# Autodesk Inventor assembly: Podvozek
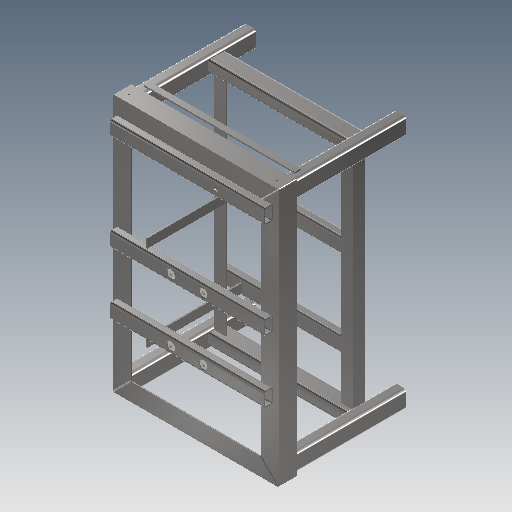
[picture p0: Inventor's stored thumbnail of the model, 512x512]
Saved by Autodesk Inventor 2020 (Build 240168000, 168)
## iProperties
Created: 2025-03
Part Number: Podvozek
Document SubType Name: Assembly
Designer: doma
Mass: 48215.9 g
Surface Area: 25160.2 cm^2
Volume: 6142.15 cm^3
Density: 7.85 g/cm^3
Author: doma
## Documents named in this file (13)
- C:\Users\doma\Desktop\Pásovka záloha\Workgroups\NotInProject\Svařenec podvozek.iam
- C:\Users\doma\Desktop\Pásovka záloha\Workgroups\NotInProject\Podvozek vinkl 870.ipt
- C:\Users\doma\Desktop\Pásovka záloha\Workgroups\NotInProject\Podvozek vinkl 560.ipt
- C:\Users\doma\Desktop\Pásovka záloha\Workgroups\NotInProject\Podvozek jekl 430.ipt
- C:\Users\doma\Desktop\Pásovka záloha\Workgroups\NotInProject\Podvozek jekl 468.ipt
- C:\Users\doma\Desktop\Pásovka záloha\Workgroups\NotInProject\Podvozek vinkl 738.ipt
- C:\Users\doma\Desktop\Pásovka záloha\Workgroups\NotInProject\Podvozek pásovina 508.ipt
- C:\Users\doma\Desktop\Pásovka záloha\Workgroups\NotInProject\Podvozek jekl 458.ipt
- C:\Users\doma\Desktop\Pásovka záloha\Workgroups\NotInProject\Matice kotevní desky.ipt
- C:\Users\doma\Desktop\Pásovka záloha\Workgroups\NotInProject\Podvozek pásovina 320.ipt
- C:\Users\doma\Desktop\Pásovka záloha\Workgroups\NotInProject\Podvozek jekl 520 1.ipt
- C:\Users\doma\Desktop\Pásovka záloha\Workgroups\NotInProject\Podvozek jekl 520 2.ipt
- C:\Users\doma\Documents\Inventor\Content Center Files\R2020\cs-CZ\CSN 02 1741\CSN 02 1741 - 5.ipt
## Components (26 placed, 12 different names)
1. Podvozek vinkl 870:1 — Stejný směr:3, Proti sobě:5, Proti sobě:6, Proti sobě:12, Proti sobě:13, Proti sobě:17, Stejný směr:52, Stejný směr:55, Proti sobě:52
2. Podvozek vinkl 870:2 — Proti sobě:1, Stejný směr:1, Stejný směr:2, Proti sobě:3, Proti sobě:9, Proti sobě:11, Proti sobě:14, Proti sobě:18, Stejný směr:54, Proti sobě:51
3. Podvozek vinkl 560:1 — Proti sobě:1, Stejný směr:1, Stejný směr:3, Proti sobě:6, Proti sobě:7, Proti sobě:8, Proti sobě:16, Proti sobě:20, Proti sobě:51, Proti sobě:52
4. Podvozek vinkl 560:2 — Stejný směr:2, Proti sobě:3, Proti sobě:5, Proti sobě:10, Proti sobě:15, Proti sobě:31, Proti sobě:35
5. Podvozek jekl 430:1 — Proti sobě:9, Proti sobě:11, Stejný směr:5, Proti sobě:16, Proti sobě:23, Stejný směr:14, Proti sobě:28
6. Podvozek jekl 430:2 — Proti sobě:10, Proti sobě:14, Stejný směr:4, Proti sobě:29, Proti sobě:30
7. Podvozek jekl 430:3 — Proti sobě:8, Proti sobě:13, Proti sobě:15, Stejný směr:4, Proti sobě:21, Proti sobě:24
8. Podvozek jekl 430:4 — Proti sobě:7, Proti sobě:12, Stejný směr:5, Proti sobě:22, Proti sobě:27
9. Podvozek jekl 520 1:1 — Stejný směr:6, Proti sobě:17, Proti sobě:19, Proti sobě:20, Proti sobě:44, Proti sobě:45, Proti sobě:48, Stejný směr:53, Stejný směr:54
10. Podvozek jekl 520 1:2 — Stejný směr:6, Proti sobě:19, Stejný směr:38, Proti sobě:42, Proti sobě:43, Proti sobě:49, Stejný směr:53
11. Podvozek jekl 520 2:1 — Proti sobě:18, Proti sobě:35, Stejný směr:55
12. Podvozek jekl 468:1 — Proti sobě:21, Proti sobě:24, Stejný směr:13
13. Podvozek jekl 468:2 — Proti sobě:22, Proti sobě:23, Stejný směr:13, Stejný směr:14, Proti sobě:25, Proti sobě:26, Stejný směr:17
14. Podvozek vinkl 738:1 — Proti sobě:26, Stejný směr:16, Proti sobě:27, Stejný směr:17
15. Podvozek vinkl 738:2 — Proti sobě:25, Stejný směr:16, Proti sobě:28, Proti sobě:32, Proti sobě:33, Proti sobě:34, Proti sobě:50
16. Podvozek pásovina 508:1 — Proti sobě:29, Proti sobě:30, Proti sobě:31
17. Podvozek jekl 458:1 — Stejný směr:18, Proti sobě:32, Proti sobě:33, Stejný směr:50
18. Podvozek jekl 458:2 — Stejný směr:18, Proti sobě:34, Proti sobě:47, Stejný směr:51
19. Matice kotevní desky:1 — Stejný směr:35, Proti sobě:45
20. Matice kotevní desky:2 — Stejný směr:36, Proti sobě:44
21. Matice kotevní desky:3 — Stejný směr:35, Stejný směr:36, Stejný směr:37, Proti sobě:43
22. Matice kotevní desky:4 — Stejný směr:37, Stejný směr:38, Proti sobě:42
23. Podvozek pásovina 320:1 — Stejný směr:48, Stejný směr:49, Proti sobě:47, Proti sobě:48, Stejný směr:51
24. Podvozek pásovina 320:2 — Stejný směr:48, Stejný směr:49, Proti sobě:49, Stejný směr:50, Stejný směr:52
25. CSN 02 1741 5:1 — Stejný směr:56
26. CSN 02 1741 5:2 — Stejný směr:56, Proti sobě:50
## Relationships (67: Mate 43, Flush 24)
- Proti sobě:1 [Mate]: Podvozek vinkl 870:2 ↔ Podvozek vinkl 560:1
- Stejný směr:1 [Flush]: Podvozek vinkl 870:2 ↔ Podvozek vinkl 560:1
- Stejný směr:2 [Flush]: Podvozek vinkl 870:2 ↔ Podvozek vinkl 560:2
- Proti sobě:3 [Mate]: Podvozek vinkl 870:2 ↔ Podvozek vinkl 560:2
- Stejný směr:3 [Flush]: Podvozek vinkl 870:1 ↔ Podvozek vinkl 560:1
- Proti sobě:5 [Mate]: Podvozek vinkl 870:1 ↔ Podvozek vinkl 560:2
- Proti sobě:6 [Mate]: Podvozek vinkl 870:1 ↔ Podvozek vinkl 560:1
- Proti sobě:7 [Mate]: Podvozek vinkl 560:1 ↔ Podvozek jekl 430:4
- Proti sobě:8 [Mate]: Podvozek vinkl 560:1 ↔ Podvozek jekl 430:3
- Proti sobě:9 [Mate]: Podvozek vinkl 870:2 ↔ Podvozek jekl 430:1
- Proti sobě:10 [Mate]: Podvozek vinkl 560:2 ↔ Podvozek jekl 430:2
- Proti sobě:11 [Mate]: Podvozek vinkl 870:2 ↔ Podvozek jekl 430:1
- Proti sobě:12 [Mate]: Podvozek vinkl 870:1 ↔ Podvozek jekl 430:4
- Proti sobě:13 [Mate]: Podvozek vinkl 870:1 ↔ Podvozek jekl 430:3
- Proti sobě:14 [Mate]: Podvozek vinkl 870:2 ↔ Podvozek jekl 430:2
- Proti sobě:15 [Mate]: Podvozek vinkl 560:2 ↔ Podvozek jekl 430:3
- Stejný směr:4 [Flush]: Podvozek jekl 430:2 ↔ Podvozek jekl 430:3
- Stejný směr:5 [Flush]: Podvozek jekl 430:1 ↔ Podvozek jekl 430:4
- Proti sobě:16 [Mate]: Podvozek vinkl 560:1 ↔ Podvozek jekl 430:1
- Stejný směr:6 [Flush]: Podvozek jekl 520 1:1 ↔ Podvozek jekl 520 1:2
- Proti sobě:17 [Mate]: Podvozek vinkl 870:1 ↔ Podvozek jekl 520 1:1
- Proti sobě:18 [Mate]: Podvozek vinkl 870:2 ↔ Podvozek jekl 520 2:1
- Proti sobě:19 [Mate]: Podvozek jekl 520 1:1 ↔ Podvozek jekl 520 1:2
- Proti sobě:20 [Mate]: Podvozek vinkl 560:1 ↔ Podvozek jekl 520 1:1
- Proti sobě:21 [Mate]: Podvozek jekl 430:3 ↔ Podvozek jekl 468:1
- Proti sobě:22 [Mate]: Podvozek jekl 430:4 ↔ Podvozek jekl 468:2
- Proti sobě:23 [Mate]: Podvozek jekl 430:1 ↔ Podvozek jekl 468:2
- Proti sobě:24 [Mate]: Podvozek jekl 430:3 ↔ Podvozek jekl 468:1
- Stejný směr:13 [Flush]: Podvozek jekl 468:1 ↔ Podvozek jekl 468:2
- Stejný směr:14 [Flush]: Podvozek jekl 430:1 ↔ Podvozek jekl 468:2
- Proti sobě:25 [Mate]: Podvozek jekl 468:2 ↔ Podvozek vinkl 738:2
- Proti sobě:26 [Mate]: Podvozek jekl 468:2 ↔ Podvozek vinkl 738:1
- Stejný směr:16 [Flush]: Podvozek vinkl 738:1 ↔ Podvozek vinkl 738:2
- Proti sobě:27 [Mate]: Podvozek jekl 430:4 ↔ Podvozek vinkl 738:1
- Proti sobě:28 [Mate]: Podvozek jekl 430:1 ↔ Podvozek vinkl 738:2
- Proti sobě:29 [Mate]: Podvozek jekl 430:2 ↔ Podvozek pásovina 508:1
- Proti sobě:30 [Mate]: Podvozek jekl 430:2 ↔ Podvozek pásovina 508:1
- Proti sobě:31 [Mate]: Podvozek vinkl 560:2 ↔ Podvozek pásovina 508:1
- Stejný směr:17 [Flush]: Podvozek jekl 468:2 ↔ Podvozek vinkl 738:1
- Stejný směr:18 [Flush]: Podvozek jekl 458:1 ↔ Podvozek jekl 458:2
- Proti sobě:32 [Mate]: Podvozek vinkl 738:2 ↔ Podvozek jekl 458:1
- Proti sobě:33 [Mate]: Podvozek vinkl 738:2 ↔ Podvozek jekl 458:1
- Proti sobě:34 [Mate]: Podvozek vinkl 738:2 ↔ Podvozek jekl 458:2
- Proti sobě:35 [Mate]: Podvozek vinkl 560:2 ↔ Podvozek jekl 520 2:1
- Stejný směr:35 [Flush]: Matice kotevní desky:1 ↔ Matice kotevní desky:3
- Stejný směr:36 [Flush]: Matice kotevní desky:2 ↔ Matice kotevní desky:3
- Stejný směr:37 [Flush]: Matice kotevní desky:3 ↔ Matice kotevní desky:4
- Stejný směr:38 [Flush]: Podvozek jekl 520 1:2 ↔ Matice kotevní desky:4
- Proti sobě:42 [Mate]: Podvozek jekl 520 1:2 ↔ Matice kotevní desky:4
- Proti sobě:43 [Mate]: Podvozek jekl 520 1:2 ↔ Matice kotevní desky:3
- Proti sobě:44 [Mate]: Podvozek jekl 520 1:1 ↔ Matice kotevní desky:2
- Proti sobě:45 [Mate]: Podvozek jekl 520 1:1 ↔ Matice kotevní desky:1
- Stejný směr:48 [Flush]: Podvozek pásovina 320:1 ↔ Podvozek pásovina 320:2
- Stejný směr:49 [Flush]: Podvozek pásovina 320:1 ↔ Podvozek pásovina 320:2
- Proti sobě:47 [Mate]: Podvozek jekl 458:2 ↔ Podvozek pásovina 320:1
- Proti sobě:48 [Mate]: Podvozek jekl 520 1:1 ↔ Podvozek pásovina 320:1
- Proti sobě:49 [Mate]: Podvozek jekl 520 1:2 ↔ Podvozek pásovina 320:2
- Stejný směr:50 [Flush]: Podvozek jekl 458:1 ↔ Podvozek pásovina 320:2
- Stejný směr:51 [Flush]: Podvozek jekl 458:2 ↔ Podvozek pásovina 320:1
- Stejný směr:52 [Flush]: Podvozek vinkl 870:1 ↔ Podvozek pásovina 320:2
- Stejný směr:53 [Flush]: Podvozek jekl 520 1:1 ↔ Podvozek jekl 520 1:2
- Stejný směr:54 [Flush]: Podvozek vinkl 870:2 ↔ Podvozek jekl 520 1:1
- Stejný směr:55 [Flush]: Podvozek vinkl 870:1 ↔ Podvozek jekl 520 2:1
- Stejný směr:56 [Flush]: CSN 02 1741 5:1 ↔ CSN 02 1741 5:2
- Proti sobě:50 [Mate]: Podvozek vinkl 738:2 ↔ CSN 02 1741 5:2
- Proti sobě:51 [Mate]: Podvozek vinkl 870:2 ↔ Podvozek vinkl 560:1
- Proti sobě:52 [Mate]: Podvozek vinkl 870:1 ↔ Podvozek vinkl 560:1
